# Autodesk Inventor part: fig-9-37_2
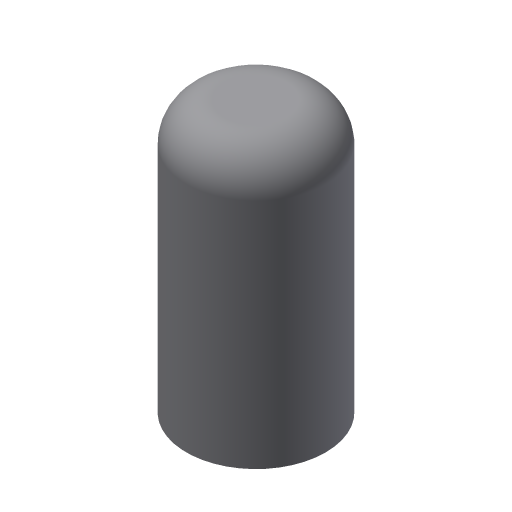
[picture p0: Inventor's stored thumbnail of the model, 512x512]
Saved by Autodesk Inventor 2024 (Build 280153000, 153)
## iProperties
Created: 2013-03
Part Number: fig-9-37_2
Material: Generic
Document SubType Name: Modeling
Designer: CADCIM
Density: 1 g/cm^3
Appearance: Default
Author: CADCIM
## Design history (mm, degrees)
sketch "Sketch1"
  geometry: C1 r 9 at (0, 0); 1 further point
  constraints: 1 centre point, 1 coincident
  dimensions: "d0" = 18 diameter of C1
extrude "Extrusion1" new body sketch "Sketch1" distance "d2" = 35; taper "d3" = 0 deg
fillet "Fillet1" dims "d4" = 5
body "Solid1"
